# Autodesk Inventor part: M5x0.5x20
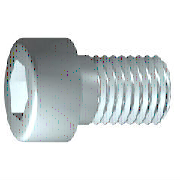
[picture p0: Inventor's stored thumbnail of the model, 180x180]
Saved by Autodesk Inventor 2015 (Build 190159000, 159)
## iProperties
IsCustomPart: 0
Company: 한국ATC센터
Created: 2014-07
Part Number: M5x0.5x20
Material: Steel, Mild
Description: 6각머리 태핑 나사
Document SubType Name: Modeling
Standard: KS B 1003
Designer: KYOUNG IL JANG
Standards Organization: KS
Language: ko-KR
Size Designation: M 5 x 20
Categories: <MemberInstance><Categories><Category DisplayName="조임쇠" InternalName="e4da775c-781d-43d5-af7c-5136215cf5a6" Mnemonic="FSTN"><Category DisplayName="볼트" InternalN
Density: 7.85 g/cm^3
Appearance: Steel
Mass: 4.95658 g
Surface Area: 5.88237 cm^2
Volume: 0.631412 cm^3
Author: KYOUNG IL JANG
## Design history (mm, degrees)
revolve "본체" stored, may be unused: angle "d10" = 90 deg
sketch "스케치2"
  geometry: L1 (0, -5.95)-(0, 5.95) reference; L2 (-5.95, 0)-(5.95, 0) reference; L3 (2.309, 0)-(1.155, -2); L4 (1.155, -2)-(-1.155, -2); L5 (-1.155, -2)-(-2.309, 0); L6 (-2.309, 0)-(-1.155, 2); L7 (-1.155, 2)-(1.155, 2); L8 (1.155, 2)-(2.309, 0); 2 further points
  constraints: 12 end point, 1 coincident, 1 horizontal alignment, 1 point on line, 12 other
extrude "슬롯" join sketch "스케치2" stored distance "d11" = 10; taper "d12" = 0 deg
workplane "Work Plane1"
fillet "Fillet2" dims "d30" = 0.1 (= R)
body "Solid1"
fillet "모깎기1" dims "d17" = 0.5 (= RR)
feature "스레드" dims "d13" = 18 (= GEL), "d14" = 0
chamfer "모따기1" distance "d15" = 0.49076 (= -0.5 x SPD + 0.5 x GD); stored, may be unused: second distance "d16" = 0.49076 (= GUL), angle "d27" = 45 deg
sketch "스케치1"
  geometry: L1 (-1.167, 0)-(20, 0); L2 (20, 0)-(20, 2.5); L3 (20, 2.5)-(2, 2.5); L4 (2, 2.5)-(1.509, 2.5); L5 (1.509, 2.5)-(0, 2.5); L6 (0, 2.5)-(0, 4.25); L7 (0, 4.25)-(-5, 4.25); L8 (-5, 4.25)-(-5, 2.309); L9 (-5, 2.309)-(-2.5, 2.309); L10 (-2.5, 2.309)-(-1.167, 0); L11 (-10, 0)-(25, 0) reference; L12 (0, -0.85)-(0, 5.1) reference; L13 (2, 2.5)-(0, 2.5)
  constraints: 22 end point, 6 parallel, 2 collinear, 2 perpendicular, 1 horizontal, 1 point on line
  dimensions: "d1" = 18 distance from line of L3.end L2 (= GEL); "d2" = 0.49086 distance of L4.end L3.end (computed from GAL); "d3" = 5 distance between parallel lines of L8 L6 (= KOH); "d4" = 2.5 distance of L8.end L9.end (= INTI); "d5" = 60 deg angle of L10 L1; "d6" = 5 diameter of L3 L1 (= GD); "d7" = 5 diameter of L5 L1 (= BDM); "d8" = 4.6188 diameter of L9 L1 (= 1.1547 x SW); "d9" = 8.5 diameter of L7 L1 (= KOD); "d26" = 20 distance between parallel lines of L12 L2 (= NLG)
other parameters: "GD" = 5 (= NND) [user parameter; used in 2 equation terms], "NLG" = 20 [user parameter; used in 1 equation term], "GEL" = 18 [user parameter; used in 2 equation terms], "KOD" = 8.5 [user parameter; used in 1 equation term], "KOH" = 5 [user parameter; used in 1 equation term], "INTI" = 2.5 [user parameter; used in 1 equation term], "GAL" = 0.49076 (= 0.61345 x PTC) [user parameter; used in 1 equation term], "GUL" = 0.49076 (= 0.61345 x PTC) [user parameter; used in 1 equation term], "BDM" = 5 (= NND) [user parameter; used in 1 equation term], "SW" = 4 [user parameter; used in 2 equation terms], "RR" = 0.5 [user parameter; used in 1 equation term], "SPD" = 4.01848 (= NND - 1.2269 x PTC) [user parameter; used in 1 equation term], "d19" = 0, "d28" = 0, "d29" = 0, "R" = 0.1 [user parameter; used in 1 equation term], "PHH" = 0.2 [user parameter], "GD1" = 4.01848 (= THREADDIA - 1.2269 x PTC) [user parameter], "THREADDIA" = 5 [user parameter; used in 1 equation term], "FAWI" = 45 deg [user parameter], "TPU" = 12.5 (computed from PTC) [user parameter], "PTC" = 0.8 [user parameter; used in 5 equation terms], "NND" = 5 [user parameter; used in 3 equation terms], "TOA" = 30 deg [user parameter], "E0" = 4.62 (= 1.155 x SW) [user parameter]
